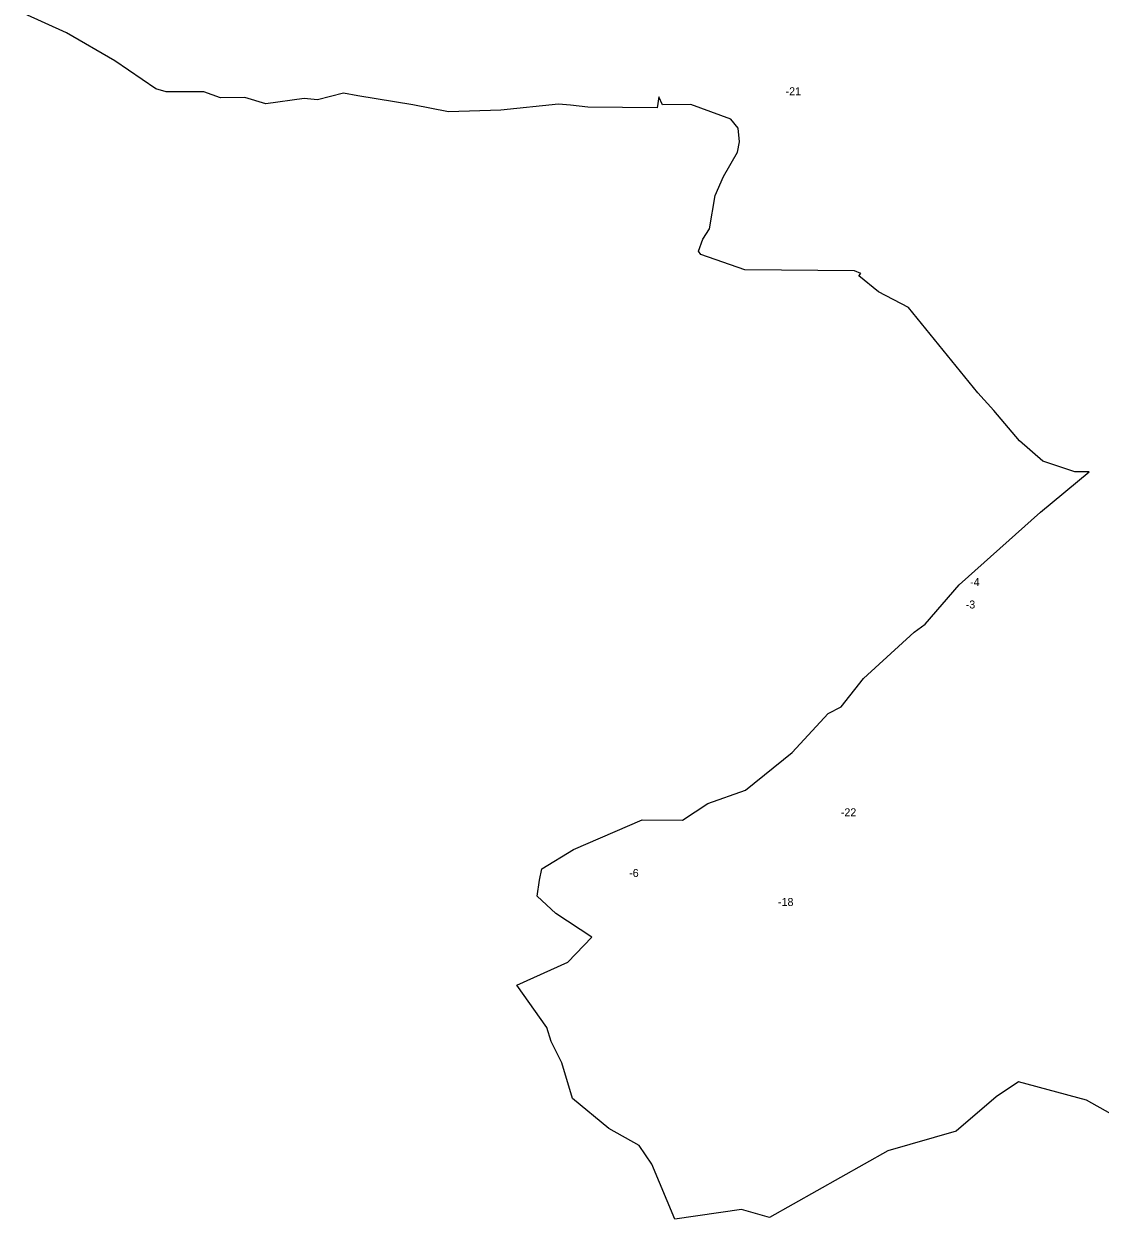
# Model space of a CAD drawing. Extents: x -791694 to -787831, y -969302 to -965696.
# Drawn here: x -791041 to -789697, y -968706 to -967213 of the extents above; entities that cross this region are included whole.
import ezdxf

# ---------------------------------------------------------------- set-up
doc = ezdxf.new("R2010")
doc.units = 0
doc.layers.add('Vrstva 13', color=7, linetype='Continuous')
doc.layers.add('Vrstva 15', color=7, linetype='Continuous')

msp = doc.modelspace()

# ---------------------------------------------------------------- linework, layer by layer
at = {"layer": 'Vrstva 13'}
for p, q in [((-790988.42, -967224.5), (-791041.43, -967200.16)), ((-790927.76, -967259.18), (-790988.42, -967224.5)), ((-790876.41, -967294.2), (-790927.76, -967259.18)), ((-790863.75, -967298.2), (-790876.41, -967294.2)), ((-790816.74, -967297.87), (-790863.75, -967298.2)), ((-790795.74, -967305.54), (-790816.74, -967297.87)), ((-790765.41, -967305.2), (-790795.74, -967305.54)), ((-790739.07, -967312.87), (-790765.41, -967305.2)), ((-790691.07, -967306.2), (-790739.07, -967312.87)), ((-790674.74, -967308.2), (-790691.07, -967306.2)), ((-790642.07, -967299.87), (-790674.74, -967308.2)), ((-790624.06, -967303.19), (-790642.07, -967299.87)), ((-790555.39, -967314.19), (-790624.06, -967303.19)), ((-790248.05, -967304.19), (-790250.05, -967318.19)), ((-790243.38, -967314.19), (-790248.05, -967304.19)), ((-790511.06, -967322.86), (-790555.39, -967314.19)), ((-790445.73, -967320.86), (-790511.06, -967322.86)), ((-790373.39, -967313.52), (-790445.73, -967320.86)), ((-790358.39, -967314.52), (-790373.39, -967313.52)), ((-790336.72, -967317.19), (-790358.39, -967314.52)), ((-790250.05, -967318.19), (-790336.72, -967317.19)), ((-790208.05, -967313.86), (-790243.38, -967314.19)), ((-790158.04, -967332.2), (-790208.05, -967313.86)), ((-790148.88, -967343.29), (-790158.04, -967332.2)), ((-790147.21, -967360.47), (-790148.88, -967343.29)), ((-790150.04, -967373.31), (-790147.21, -967360.47)), ((-790167.38, -967403.82), (-790150.04, -967373.31)), ((-790177.71, -967427.66), (-790167.38, -967403.82)), ((-790185.04, -967469.35), (-790177.71, -967427.66)), ((-790193.21, -967482.02), (-790185.04, -967469.35)), ((-790198.55, -967497.02), (-790193.21, -967482.02)), ((-790195.88, -967501.35), (-790198.55, -967497.02)), ((-790140.55, -967520.53), (-790195.88, -967501.35)), ((-790003.88, -967521.53), (-790140.55, -967520.53)), ((-789995.71, -967524.86), (-790003.88, -967521.53)), ((-789998.38, -967527.95), (-789995.71, -967524.86)), ((-789973.72, -967547.96), (-789998.38, -967527.95)), ((-789936.38, -967567.3), (-789973.72, -967547.96)), ((-789849.71, -967674.01), (-789936.38, -967567.3)), ((-789829.71, -967696.02), (-789849.71, -967674.01)), ((-789797.71, -967734.03), (-789829.71, -967696.02)), ((-789768.21, -967759.29), (-789797.71, -967734.03)), ((-789728.54, -967772.63), (-789768.21, -967759.29)), ((-789771.38, -967823.23), (-789710.37, -967772.63)), ((-789710.37, -967772.63), (-789728.54, -967772.63)), ((-789873.05, -967913.94), (-789771.38, -967823.23)), ((-789915.38, -967962.96), (-789873.05, -967913.94)), ((-789929.05, -967972.96), (-789915.38, -967962.96)), ((-789992.39, -968030.99), (-789929.05, -967972.96)), ((-790020.39, -968066.34), (-789992.39, -968030.99)), ((-790036.72, -968074.67), (-790020.39, -968066.34)), ((-790081.72, -968123.36), (-790036.72, -968074.67)), ((-790139.73, -968170.37), (-790081.72, -968123.36)), ((-790187.06, -968187.05), (-790139.73, -968170.37)), ((-790218.39, -968208.06), (-790187.06, -968187.05)), ((-790354.73, -968244.74), (-790269.06, -968207.39)), ((-790269.06, -968207.39), (-790218.39, -968208.06)), ((-790394.4, -968268.75), (-790354.73, -968244.74)), ((-790397.4, -968283.09), (-790394.4, -968268.75)), ((-790400.06, -968302.76), (-790397.4, -968283.09)), ((-790377.06, -968324.77), (-790400.06, -968302.76)), ((-790332.06, -968354.28), (-790377.06, -968324.77)), ((-790362.06, -968385.63), (-790332.06, -968354.28)), ((-790425.4, -968414.31), (-790362.06, -968385.63)), ((-790388.06, -968467), (-790425.4, -968414.31)), ((-790382.73, -968484.34), (-790388.06, -968467)), ((-790369.4, -968511.02), (-790382.73, -968484.34)), ((-790356.06, -968555.7), (-790369.4, -968511.02)), ((-789798.7, -968535.03), (-789826.7, -968553.7)), ((-789714.03, -968557.7), (-789798.7, -968535.03)), ((-790310.73, -968593.05), (-790356.06, -968555.7)), ((-789826.7, -968553.7), (-789876.7, -968596.39)), ((-789683.36, -968575.04), (-789714.03, -968557.7)), ((-790272.72, -968614.39), (-790310.73, -968593.05)), ((-789876.7, -968596.39), (-789962.04, -968621.06)), ((-790256.72, -968637.73), (-790272.72, -968614.39)), ((-789962.04, -968621.06), (-790110.05, -968704.43)), ((-790228.06, -968706.43), (-790256.72, -968637.73)), ((-790144.72, -968694.42), (-790228.06, -968706.43)), ((-790110.05, -968704.43), (-790144.72, -968694.42))]:
    msp.add_line(p, q, dxfattribs=at)

# ---------------------------------------------------------------- texts
at = {"layer": 'Vrstva 15'}
for s, p in [('-21', (-790089.794, -967302.34)), ('-4', (-789859.346, -967915.53)), ('-3', (-789864.77, -967943.54)), ('-22', (-790020.8, -968203.21)), ('-6', (-790285.234, -968279.03)), ('-18', (-790099.294, -968315.24))]:
    msp.add_text(s, height=10, dxfattribs=at).set_placement(p)

doc.saveas('drawing.dxf')
